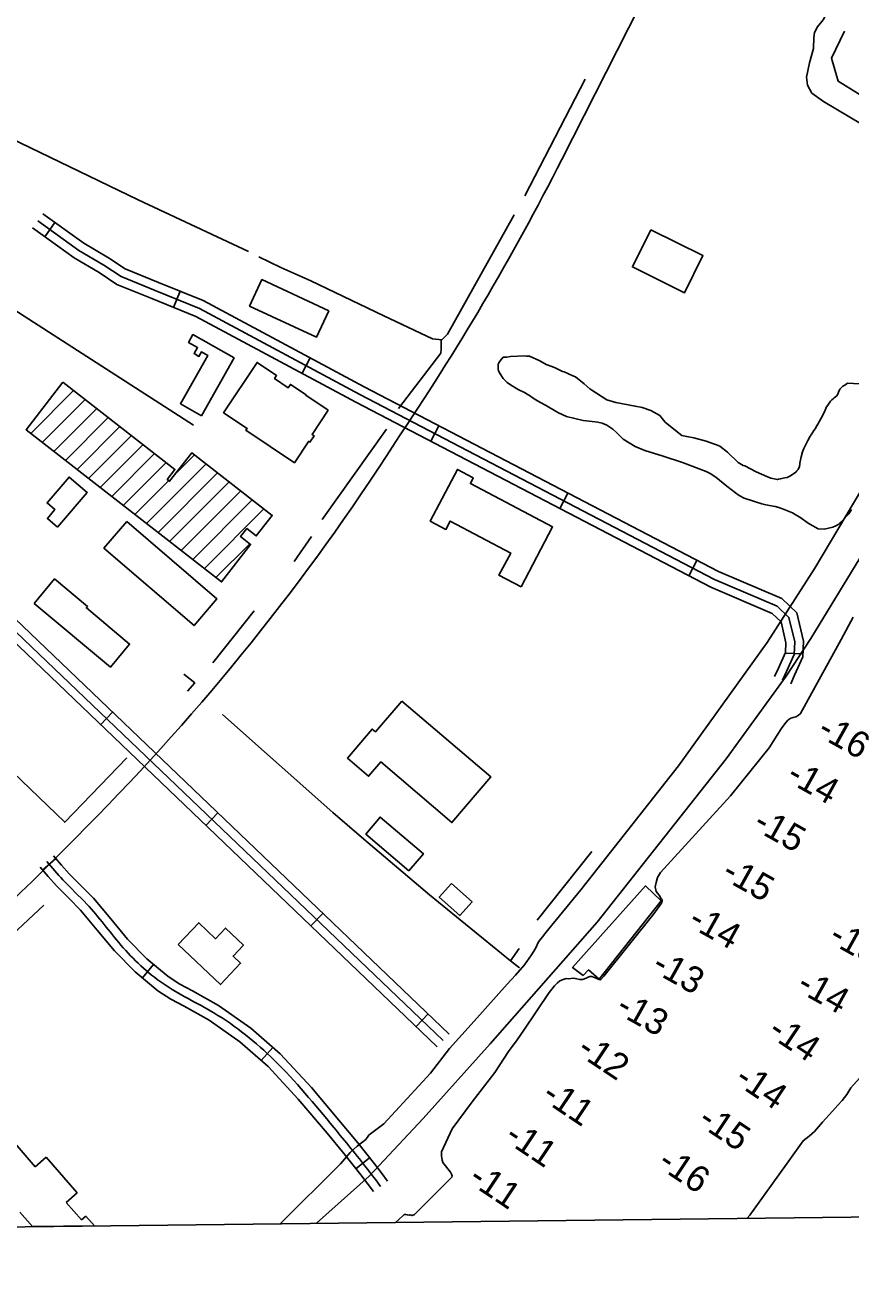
# Model space of a CAD drawing. Extents: x 3683402 to 3721514, y 487807 to 513565.
# Drawn here: x 3695359 to 3696778, y 493222 to 495375 of the extents above; entities that cross this region are included whole.
import ezdxf

# ---------------------------------------------------------------- set-up
doc = ezdxf.new("R2010")
doc.units = 0
for name, color, linetype in [('V-BLDG-OTLN', 7, 'Continuous'), ('V-CHAN-DOCK', 7, 'Continuous'), ('V-FLOD-BASE', 7, 'Continuous'), ('V-GRID-FRAM', 7, 'Continuous'), ('V-LEVE-TOET', 7, 'Continuous'), ('V-ROAD-CNTR', 7, 'Continuous'), ('V-SITE-VEGE', 7, 'Continuous'), ('V-TOPO-SHOR', 7, 'Continuous'), ('V-TOPO-SPOT', 7, 'Continuous')]:
    doc.layers.add(name, color=color, linetype=linetype)

msp = doc.modelspace()

# ---------------------------------------------------------------- linework, layer by layer
at = {"layer": 'V-BLDG-OTLN'}
for p, q in [((3695368.7, 494673.7), (3695442.3, 494747.2)), ((3695388.6, 494658.2), (3695462.2, 494731.8)), ((3695408.5, 494642.8), (3695482.1, 494716.3)), ((3695428.4, 494627.3), (3695501.9, 494700.8)), ((3695448.3, 494611.8), (3695521.8, 494685.3)), ((3695468.2, 494596.3), (3695541.7, 494669.9)), ((3695488.1, 494580.9), (3695561.6, 494654.4)), ((3695508, 494565.4), (3695581.5, 494638.9)), ((3695616.7, 494603.5), (3695650, 494636.7)), ((3695527.8, 494549.9), (3695601.4, 494623.5)), ((3695567.6, 494519), (3695669.9, 494621.3)), ((3695547.7, 494534.5), (3695605.9, 494592.7)), ((3695587.5, 494503.5), (3695689.8, 494605.8)), ((3695607.4, 494488.1), (3695709.7, 494590.3)), ((3695627.3, 494472.6), (3695729.5, 494574.9)), ((3695647.2, 494457.1), (3695749.4, 494559.4)), ((3695667, 494441.7), (3695769.3, 494543.9)), ((3695686.9, 494426.2), (3695744.9, 494484.2)), ((3695310.3, 493490.6), (3695376.3, 493414.2)), ((3695376.3, 493414.2), (3695395.5, 493430.7)), ((3695395.5, 493430.7), (3695448.4, 493369.4)), ((3695448.4, 493369.4), (3695429.8, 493353.3)), ((3695429.8, 493353.3), (3695455.9, 493323.1)), ((3695371.7, 493311.7), (3695350.1, 493336.6)), ((3695455.9, 493323.1), (3695463.6, 493329.8)), ((3695463.6, 493329.8), (3695478.2, 493312.9)), ((3695478.2, 493312.9), (3695371.7, 493311.7))]:
    msp.add_line(p, q, dxfattribs=at)
for points in [[(3696433.8, 495023.3), (3696523.5, 494979), (3696491.9, 494915.2), (3696402.3, 494959.5)], [(3695880.7, 494884.1), (3695859.6, 494838.9), (3695744.8, 494892.4), (3695765.9, 494937.7)], [(3695662.2, 494704.1), (3695625.9, 494724.6), (3695672.8, 494807.5), (3695662.1, 494813.6), (3695657.8, 494806), (3695649.4, 494810.8), (3695655.3, 494821.2), (3695639.8, 494830), (3695647.3, 494843.3), (3695718.2, 494803.2)], [(3695880, 494713.5), (3695852.2, 494671.8), (3695855.7, 494669.4), (3695848.5, 494658.6), (3695846.3, 494660.1), (3695821.6, 494623.2), (3695738.3, 494679), (3695740.5, 494682.3), (3695700, 494709.3), (3695757.7, 494795.5), (3695791.2, 494773.1), (3695787.6, 494767.7), (3695811, 494752), (3695815, 494757.9), (3695841.8, 494740), (3695841.4, 494739.3)], [(3695423.9, 494761.5), (3695616.4, 494611.8), (3695603.2, 494594.8), (3695607.4, 494591.5), (3695645.4, 494640.3), (3695783.6, 494532.8), (3695756.2, 494497.6), (3695740, 494510.2), (3695729.3, 494496.4), (3695746.5, 494483), (3695696.5, 494418.8), (3695360.6, 494680.1)], [(3696211.1, 494410.2), (3696173.2, 494430.1), (3696193.3, 494468.3), (3696089.5, 494523), (3696082, 494508.7), (3696055, 494523), (3696101.8, 494611.8), (3696129.1, 494597.3), (3696124, 494587.6), (3696265.4, 494513.1)], [(3695414.7, 494512.6), (3695397.3, 494527.4), (3695410.4, 494542.8), (3695396.8, 494554.3), (3695434.6, 494598.8), (3695465.6, 494572.5)], [(3695533.8, 494522.6), (3695688.7, 494389.6), (3695649.4, 494343.8), (3695494.5, 494476.8)], [(3695374.6, 494381.8), (3695409.6, 494423.7), (3695466.3, 494376.3), (3695464.3, 494373.9), (3695538.6, 494311.9), (3695505.6, 494272.4)], [(3696006.1, 494214.1), (3696159.2, 494083.8), (3696092.4, 494005.3), (3695970.1, 494109.5), (3695949.2, 494085), (3695912.7, 494116.1), (3695955.2, 494166.1), (3695961, 494161.1)], [(3696018.5, 493922.6), (3695944.2, 493985.7), (3695968.9, 494014.9), (3696043.3, 493951.8)], [(3696091.6, 493901), (3696127, 493869.5), (3696105.9, 493845.8), (3696070.5, 493877.3)], [(3695622.1, 493795.8), (3695657.5, 493833.3), (3695686.2, 493806), (3695703.4, 493824.2), (3695734.2, 493795.1), (3695716.3, 493776.2), (3695729.2, 493763.9), (3695694.6, 493727.3)]]:
    msp.add_lwpolyline(points, close=True, dxfattribs=at)
at = {"layer": 'V-CHAN-DOCK'}
msp.add_lwpolyline([(3696452, 493871), (3696345.4, 493736.4), (3696327.1, 493752.4), (3696317.6, 493742.9), (3696299.6, 493756.5), (3696425.1, 493896.7), (3696452, 493871)], dxfattribs=at)
at = {"layer": 'V-FLOD-BASE'}
msp.add_lwpolyline([(3696766.9, 495364.4), (3696744.5, 495318.1), (3696755.8, 495278.6), (3696954.4, 495155.3), (3697065, 495085.7), (3697081.2, 495048.7)], dxfattribs=at)
at = {"layer": 'V-GRID-FRAM'}
msp.add_lwpolyline([(3687448, 511403.5), (3719130.8, 511772.1), (3719350.3, 493590.7), (3687651.7, 493221.8), (3687448, 511403.5)], dxfattribs=at)
at = {"layer": 'V-LEVE-TOET'}
for points in [[(3696782.6, 495489.1), (3696770.9, 495467.6), (3696747.6, 495417.8), (3696730.3, 495383.6), (3696720.3, 495371.8), (3696715.2, 495362.1), (3696714.3, 495353.3), (3696713.7, 495334.5), (3696706.9, 495310.1), (3696701.5, 495285.4), (3696703.2, 495271.9), (3696710.7, 495258), (3696730.8, 495243.8), (3696881.9, 495154)], [(3696850.3, 494668.2), (3696715.8, 494442.3), (3696634, 494314.5), (3696481.4, 494103.1), (3696313.8, 493889.7), (3696258.9, 493823), (3696240.8, 493800.9), (3696235.8, 493789), (3696229.3, 493778.5), (3696217.1, 493761.4), (3696201.8, 493743.5), (3696187, 493727.7), (3696130.8, 493664.5), (3696088, 493617.4), (3696055.3, 493575.3), (3695975.3, 493488), (3695952.3, 493470.9), (3695949.5, 493468.7), (3695944.3, 493461.4), (3695929.6, 493449.8), (3695917.6, 493438.9), (3695907.5, 493427.3), (3695901, 493419.2), (3695797, 493316.6)], [(3695859.6, 493317.4), (3695949.9, 493398.4), (3696043, 493497.2), (3696158, 493625.8), (3696342.1, 493834.7), (3696563.5, 494115), (3696666.4, 494256.7), (3696709.1, 494321.6), (3696828.3, 494516.7), (3696897.4, 494628.8)]]:
    msp.add_lwpolyline(points, dxfattribs=at)
at = {"layer": 'V-ROAD-CNTR'}
for p, q in [((3695392.8, 495011.5), (3695410.3, 495035.9)), ((3695614, 494890.1), (3695625.2, 494917.9)), ((3695834.8, 494776.9), (3695849, 494803.3)), ((3696056.1, 494660.2), (3696069.9, 494686.8)), ((3696277.8, 494544.6), (3696291.6, 494571.2)), ((3696499.4, 494429.1), (3696513.3, 494455.7)), ((3696665.3, 494296.6), (3696695.2, 494295)), ((3695488.5, 494173.3), (3695509.3, 494195)), ((3695669.3, 494000.6), (3695690, 494022.3)), ((3695389.2, 493924), (3695411.9, 493943.5)), ((3695850, 493827.9), (3695870.7, 493849.5)), ((3695560.5, 493738.9), (3695579.6, 493762)), ((3696030.7, 493655.1), (3696051.5, 493676.8)), ((3695764.8, 493596.9), (3695784.5, 493619.5)), ((3695927.5, 493411), (3695950.9, 493429.7))]:
    msp.add_line(p, q, dxfattribs=at)
for points in [[(3698293, 499106.4), (3697311.1, 497172.2), (3696281.3, 495144.1)], [(3696660.5, 494250), (3696667, 494264.6), (3696680.1, 494293.8), (3696681.3, 494315.6), (3696671.3, 494357.7), (3696651, 494377.3), (3696543.6, 494422.9), (3695934.4, 494740.5), (3695658.8, 494888.2), (3695582.5, 494919), (3695523.9, 494942.9), (3695494.5, 494962.5), (3695451.6, 494987.7), (3695380.7, 495038.6)], [(3696674.3, 494243.9), (3696680.7, 494258.5), (3696695, 494290.3), (3696696.4, 494317), (3696684.9, 494365.4), (3696659.4, 494390), (3696550.1, 494436.5), (3695941.4, 494753.8), (3695665.1, 494901.8), (3695588.1, 494932.9), (3695530.9, 494956.2), (3695502.5, 494975.2), (3695459.8, 495000.3), (3695389.4, 495050.8)], [(3696646.8, 494256), (3696653.3, 494270.7), (3696665.3, 494297.4), (3696666.2, 494314.3), (3696657.8, 494349.9), (3696642.6, 494364.5), (3696537.2, 494409.4), (3695927.4, 494727.3), (3695652.4, 494874.6), (3695576.8, 494905.1), (3695516.8, 494929.6), (3695486.5, 494949.8), (3695443.4, 494975.1), (3695371.9, 495026.5)], [(3696087.6, 493642.3), (3695328, 494368.3), (3695233.2, 494465.8), (3695093.1, 494595.2)], [(3696066.9, 493620.6), (3695306.9, 494347), (3695212.3, 494444.4), (3695072.8, 494573.1)], [(3696077.2, 493631.4), (3695317.4, 494357.6), (3695222.8, 494455.1), (3695082.9, 494584.1)], [(3695981.8, 493389.8), (3695970.7, 493404.5), (3695959.3, 493419.2), (3695930.4, 493455.4), (3695901, 493491.2), (3695850.8, 493550.4), (3695797.5, 493608.3), (3695746.6, 493652.5), (3695691.4, 493691.3), (3695646.7, 493716.5), (3695624.8, 493728.2), (3695604.9, 493741.1), (3695568.3, 493771.3), (3695534.8, 493805.2), (3695506.2, 493840), (3695476.4, 493875.5), (3695455.3, 493896.7), (3695435, 493917.4), (3695421.3, 493932.5), (3695407.8, 493948.2)], [(3695957.8, 493371.8), (3695946.8, 493386.3), (3695935.8, 493400.7), (3695907.1, 493436.5), (3695878, 493472), (3695828.3, 493530.6), (3695776.5, 493586.7), (3695728, 493628.8), (3695675.4, 493665.9), (3695632.3, 493690.2), (3695609.6, 493702.4), (3695587.1, 493716.8), (3695548, 493749.1), (3695512.5, 493785.1), (3695483.1, 493820.9), (3695454.3, 493855.2), (3695434, 493875.6), (3695413.1, 493896.8), (3695398.8, 493912.7), (3695385.1, 493928.7)]]:
    msp.add_lwpolyline(points, dxfattribs=at)
for centre, radius, start, end in [((3692223.5, 497207.3), 4552.1, 325.9446, 333.0484), ((3692613.2, 496832.6), 4020.5, 315.171, 327.2592), ((3692172.5, 497192.6), 4587.2, 305.2715, 315.862)]:
    msp.add_arc(centre, radius, start, end, dxfattribs=at)
msp.add_spline([(3695969.8, 493380.8), (3695947.6, 493409.9), (3695889.5, 493481.6), (3695787, 493597.5), (3695683.4, 493678.6), (3695596, 493729), (3695523.7, 493795.1), (3695465.3, 493865.3), (3695424, 493907.1), (3695396.5, 493938.5)], degree=3, dxfattribs=at)
at = {"layer": 'V-SITE-VEGE'}
for points in [[(3696779, 494543.3), (3696774, 494535.4), (3696763.6, 494524.1), (3696760.7, 494521.3), (3696758.2, 494518.6), (3696752.1, 494515.2), (3696746.8, 494512.5), (3696731.8, 494509.3), (3696721.8, 494509.6), (3696707.5, 494517.7), (3696704.4, 494519.8), (3696690.2, 494529.9), (3696685.1, 494532.8), (3696677.2, 494537.1), (3696660.5, 494544.4), (3696654.1, 494546.6), (3696647.4, 494548.4), (3696631.8, 494550.9), (3696624.6, 494552.7), (3696613.8, 494556.2), (3696610.3, 494557.5), (3696594.3, 494562.4), (3696586, 494567.1), (3696579.3, 494571.7), (3696564.4, 494583), (3696545.6, 494598.4), (3696536.1, 494605.1), (3696529, 494608.2), (3696488.5, 494623.8), (3696455, 494634.4), (3696424, 494644.6), (3696406.9, 494651.1), (3696386.8, 494663.8), (3696375.1, 494675), (3696368.8, 494681.2), (3696358.6, 494687.9), (3696350.6, 494691), (3696343, 494692.8), (3696333.4, 494693.9), (3696317.8, 494696), (3696289.1, 494702.8), (3696275.2, 494708.9), (3696271.3, 494711.4), (3696253.1, 494722.4), (3696243.2, 494727.5), (3696236.5, 494731.3), (3696231.8, 494734.3), (3696225.5, 494738.9), (3696220.7, 494741.4), (3696218.4, 494743.1), (3696206.1, 494749.1), (3696192.7, 494757.1), (3696187.1, 494760.9), (3696180.5, 494767.9), (3696175.1, 494775.7), (3696172.5, 494781), (3696171.7, 494783.4), (3696171.5, 494789.9), (3696172, 494792.7), (3696172.9, 494794.7), (3696175.4, 494798.2), (3696180.4, 494804.5)], [(3696180.4, 494804.5), (3696182.4, 494804.8), (3696186.4, 494804.7), (3696192.9, 494805.7), (3696217.4, 494807), (3696220.2, 494806.5), (3696225.5, 494806.4), (3696243.3, 494798.2), (3696254.4, 494791.9), (3696268.3, 494786.6), (3696282.5, 494780.2), (3696285.3, 494779.3), (3696300, 494772.8), (3696304.4, 494770.7), (3696319.7, 494759), (3696329.1, 494750.3), (3696332.6, 494747.8), (3696358.6, 494731.3), (3696373.8, 494726.9), (3696406.9, 494720.2), (3696419.3, 494717.9), (3696434, 494713), (3696449.5, 494704.5), (3696456.1, 494696.7), (3696459.2, 494692.6), (3696487.4, 494670.1), (3696495.8, 494668.2), (3696508.2, 494666.2), (3696529.3, 494660.4), (3696536.9, 494657.7), (3696543.6, 494655.1), (3696546.8, 494654.2), (3696552.8, 494652), (3696565.7, 494641.2), (3696584.1, 494623.8), (3696592.8, 494618.7), (3696595.6, 494617.8), (3696615, 494607.6), (3696633.2, 494599.8), (3696640, 494596.8), (3696651.5, 494594.5), (3696653.6, 494595.2), (3696656.4, 494595.5), (3696664.5, 494597.3), (3696668.1, 494598), (3696674.2, 494601), (3696682.9, 494607.2), (3696684.9, 494609.2), (3696687, 494611.9), (3696689.2, 494617.1), (3696690.1, 494620.7), (3696690.1, 494622.7), (3696692.1, 494633.5), (3696694.7, 494641.8), (3696696.9, 494647.8), (3696699.5, 494653.3), (3696703.8, 494661.7), (3696707.6, 494668.8), (3696709.7, 494671.5), (3696712.2, 494675.9), (3696714.3, 494678.6), (3696716.4, 494681.8), (3696719, 494686.9), (3696720.7, 494689.7), (3696729.5, 494705.1), (3696733.4, 494713.4), (3696736, 494719.4), (3696738.1, 494722.1), (3696742.7, 494728.8), (3696744.8, 494731.6), (3696747.2, 494733.1), (3696748.9, 494734.7), (3696753.4, 494738.1), (3696755.5, 494741.3), (3696756.4, 494744.5), (3696759, 494749.6), (3696760.7, 494751.6), (3696764, 494754.7), (3696767.2, 494756.6), (3696771.8, 494760.1)], [(3696771.8, 494760.1), (3696803, 494758.4)]]:
    msp.add_lwpolyline(points, dxfattribs=at)
at = {"layer": 'V-TOPO-SHOR'}
for p, q in [((3696321.1, 495282.2), (3696217.5, 495081.5)), ((3695869.2, 494525.6), (3695979.7, 494681.2)), ((3695821.4, 494453.8), (3695851, 494496.6)), ((3695681.6, 494279.9), (3695752.5, 494368.8)), ((3695887.6, 494022.6), (3695698.4, 494191)), ((3696332.8, 493955.9), (3696238.6, 493838)), ((3695308.4, 493786.6), (3695391.1, 493863.9)), ((3696208.1, 493789.5), (3696193.2, 493768.3))]:
    msp.add_line(p, q, dxfattribs=at)
for points in [[(3695742.6, 494985.9), (3695553.1, 495074.7), (3695333.7, 495180.5)], [(3696199.1, 495049.2), (3696084.8, 494844), (3696075.1, 494834.5), (3696059.1, 494835.8), (3695975.6, 494875.5), (3695850.2, 494935.4), (3695798.6, 494958.6), (3695760.8, 494977)], [(3695648.1, 494687.7), (3695281, 494923.4), (3695229.4, 494952.8)], [(3696000.5, 494716.6), (3696073.3, 494811.7), (3696074.1, 494818.5), (3696073.6, 494834.6)], [(3695534.1, 494116.8), (3695427.3, 494006.1), (3695084, 494335.1), (3695075.1, 494351.2), (3695072.8, 494358.8), (3695064.9, 494372.3), (3695057.4, 494379), (3695048, 494384.9), (3695038.2, 494391.8), (3695026.6, 494400.3), (3695008.6, 494410.8), (3694964.9, 494431.9), (3694951.7, 494437.3), (3694943.3, 494440), (3694937.7, 494442.7), (3694932.5, 494447.4), (3694927.4, 494451.9)], [(3696347.9, 493735.8), (3696353.5, 493741.5), (3696439.4, 493848.6), (3696452.4, 493866.8), (3696453.7, 493871.1), (3696453.4, 493873.2), (3696452, 493874.4), (3696448.1, 493880.6), (3696445.3, 493884), (3696443.1, 493887.1), (3696441.4, 493895), (3696443, 493902.7), (3696445.7, 493911), (3696450.9, 493919.8), (3696570.8, 494051.5), (3696637.2, 494134), (3696658, 494166.6), (3696664, 494174.8), (3696669.5, 494181.4), (3696674.6, 494184.9), (3696678.7, 494185.8), (3696682.9, 494187.2), (3696687.4, 494189.2), (3696691.2, 494192.6), (3696700.7, 494210.2), (3696761, 494319.8), (3696781.6, 494358.1)], [(3695631.7, 494260.4), (3695650.6, 494245.3), (3695638.3, 494230.8)], [(3696208.3, 493756.1), (3696193.2, 493768.3), (3696053.6, 493881.1), (3695940.8, 493976.8), (3695887.6, 494022.6)], [(3697047.1, 493916.5), (3697016.4, 493871.4), (3696980.6, 493822.2), (3696943.8, 493765.5), (3696929.3, 493739.2), (3696908, 493699.8), (3696892.4, 493675.5), (3696874.3, 493649.9), (3696863.1, 493638.4), (3696831.3, 493608.7), (3696812.4, 493589), (3696777.9, 493549.7), (3696770.7, 493538.6), (3696762.6, 493528.4), (3696755.5, 493520.4), (3696746, 493509.8), (3696729.1, 493491.1), (3696715.1, 493474.9), (3696706.3, 493467), (3696695.6, 493459.1), (3696666.9, 493418.9), (3696604.3, 493331.6), (3696599.4, 493326)], [(3695995.3, 493318.9), (3696007.8, 493330.1), (3696010.1, 493332.4), (3696012.7, 493332.7), (3696015.9, 493331.8), (3696018.7, 493331.5), (3696020.5, 493331.7), (3696024, 493330.7), (3696027.9, 493332.7), (3696092.1, 493396.3), (3696092.6, 493398.7), (3696092.3, 493400.3), (3696089.7, 493405.3), (3696076.8, 493421.5), (3696075.6, 493425.7), (3696074.7, 493433), (3696074.6, 493440.1), (3696092.6, 493479.4), (3696127.2, 493526), (3696166.3, 493576.4), (3696189.8, 493612.5), (3696204.2, 493632.2), (3696215.6, 493648.8), (3696259.6, 493713.5), (3696268.4, 493724.9), (3696273.5, 493730.1), (3696277.9, 493733.7), (3696283.4, 493736.2), (3696288.6, 493737.6), (3696292.7, 493737.3), (3696301.4, 493738.1), (3696307, 493737), (3696311.9, 493735.9), (3696316.8, 493736.1), (3696320.2, 493737.2), (3696324.2, 493739), (3696327.8, 493740.4), (3696329.4, 493741.1), (3696332.8, 493741), (3696335.8, 493740), (3696339.9, 493738.1), (3696343.4, 493736.3), (3696346.4, 493735.6), (3696347.9, 493735.8)]]:
    msp.add_lwpolyline(points, dxfattribs=at)

# ---------------------------------------------------------------- texts
at = {"layer": 'V-TOPO-SPOT'}
for s, rotation, p in [('-16', 330.7933, (3696717.7, 494155.4)), ('-14', 330.7933, (3696664.6, 494077.5)), ('-15', 330.7933, (3696607.4, 493995.2)), ('-15', 330.7933, (3696553.3, 493910.4)), ('-14', 330.7933, (3696495.9, 493828.6)), ('-15', 330.7933, (3696737.3, 493800.9)), ('-13', 330.7933, (3696433.3, 493751.3)), ('-14', 330.7933, (3696682.3, 493717.6)), ('-13', 330.7933, (3696371.5, 493679.4)), ('-14', 326.2505, (3696632.8, 493640.9)), ('-12', 326.2505, (3696304.7, 493609.2)), ('-14', 326.2505, (3696575.8, 493558.7)), ('-11', 326.2505, (3696244.3, 493530.5)), ('-15', 326.2505, (3696512.6, 493487.8)), ('-11', 326.2505, (3696180.4, 493459.8)), ('-16', 326.2505, (3696443.4, 493415)), ('-11', 326.2505, (3696118.4, 493387.8))]:
    msp.add_text(s, height=45, rotation=rotation, dxfattribs=at).set_placement(p)

doc.saveas('drawing.dxf')
